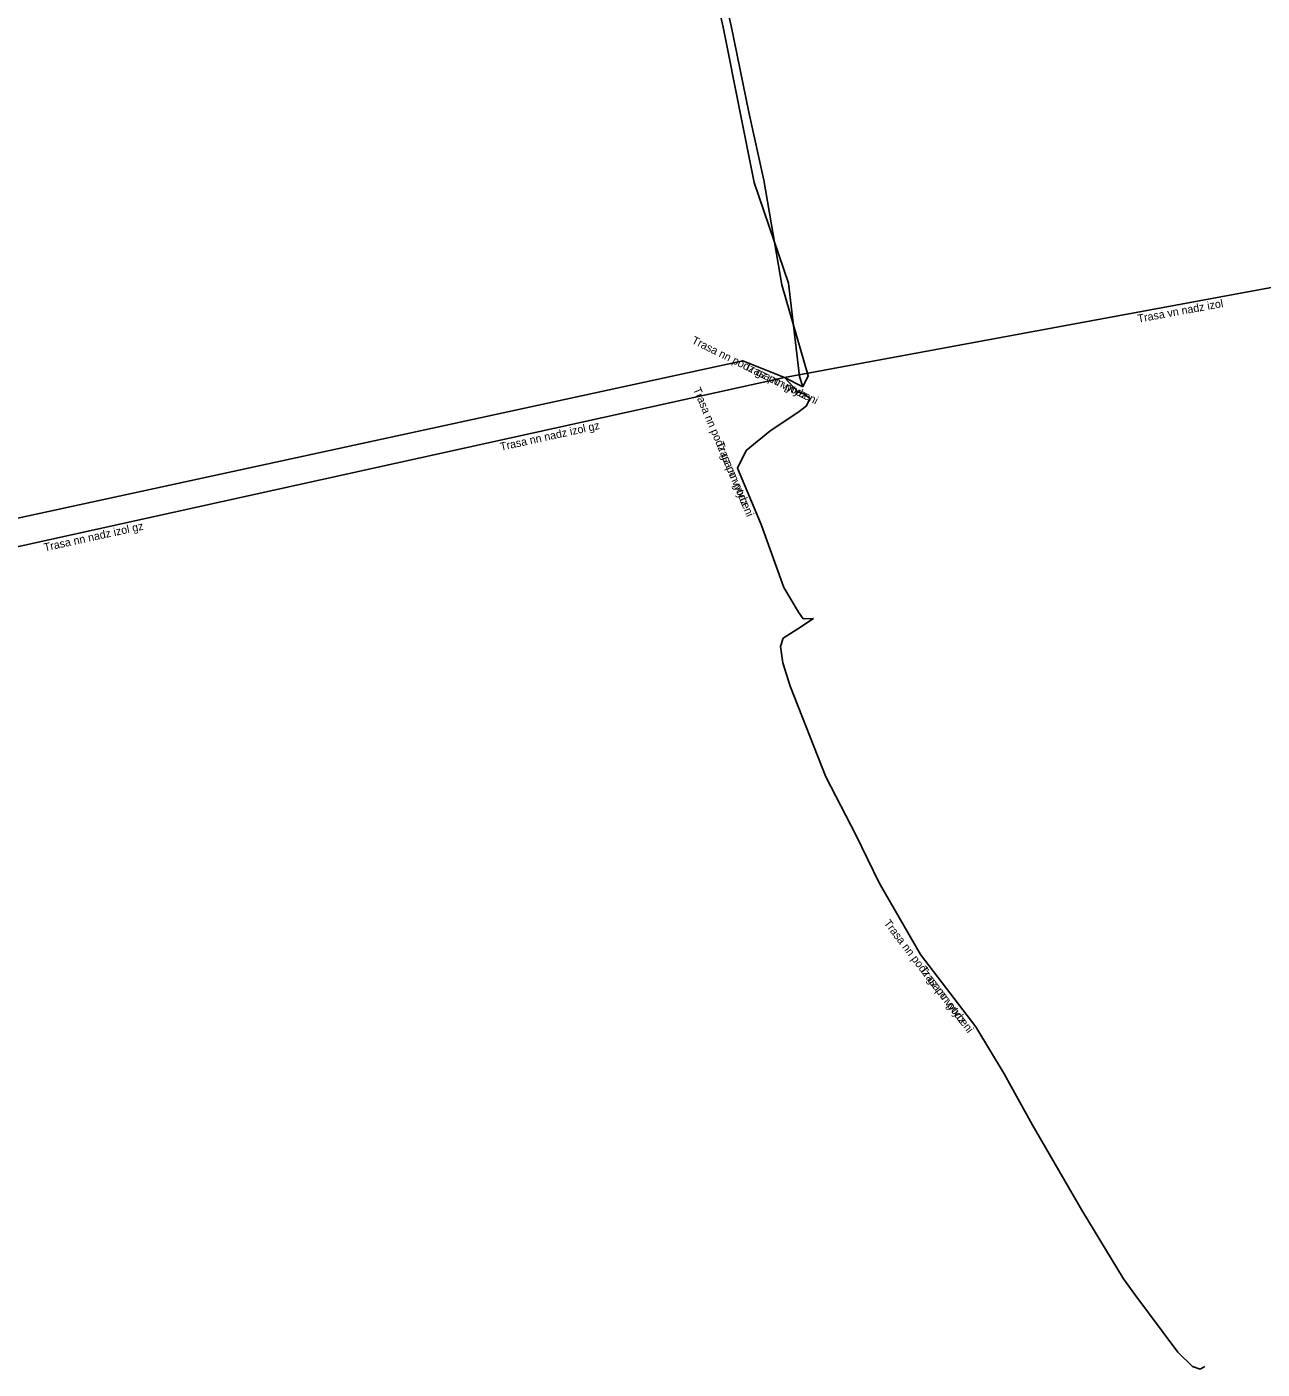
# Model space of a CAD drawing. Extents: x -876384 to -875659, y -1020218 to -1019588.
# Drawn here: x -876045.3 to -875968.1, y -1020120.4 to -1020036.5 of the extents above; entities that cross this region are included whole.
import ezdxf

# ---------------------------------------------------------------- set-up
doc = ezdxf.new("R2010")
doc.units = 0
for name, color, linetype in [('Popiskový text - Ostatní atributy Trasy', 7, 'Continuous'), ('Spojnice NN', 7, 'Continuous'), ('Spojnice VN', 7, 'Continuous')]:
    doc.layers.add(name, color=color, linetype=linetype)

msp = doc.modelspace()

# ---------------------------------------------------------------- linework, layer by layer
at = {"layer": 'Spojnice NN'}
for points in [[(-876006.23, -1020010.08), (-876006.58, -1020010.47), (-876007.09, -1020011.09), (-876007.16, -1020012.14), (-876006.39, -1020017.14), (-876004.42, -1020023.09), (-876003.38, -1020029.52), (-876001.78, -1020036.52), (-876000.71, -1020041.94), (-875999.84, -1020046.22), (-875997.71, -1020052.52), (-875997.02, -1020058.35), (-875996.81, -1020058.98)], [(-876006.23, -1020010.08), (-876006.58, -1020010.47), (-876007.09, -1020011.09), (-876007.16, -1020012.14), (-876006.39, -1020017.14), (-876004.42, -1020023.09), (-876003.38, -1020029.52), (-876001.78, -1020036.52), (-876000.71, -1020041.94), (-875999.84, -1020046.22), (-875997.71, -1020052.52), (-875997.02, -1020058.35), (-875996.81, -1020058.98)], [(-876007.97, -1020010.49), (-876007.54, -1020010.71), (-876007.4, -1020011.1), (-876006.73, -1020012.04), (-876005.81, -1020016.98), (-876004.99, -1020023.28), (-876002.91, -1020029.39), (-876001.28, -1020036.42), (-876000.18, -1020041.82), (-875999.24, -1020046.07), (-875998.13, -1020052.62), (-875996.48, -1020058.31), (-875996.81, -1020058.98)], [(-876007.97, -1020010.49), (-876007.54, -1020010.71), (-876007.4, -1020011.1), (-876006.73, -1020012.04), (-876005.81, -1020016.98), (-876004.99, -1020023.28), (-876002.91, -1020029.39), (-876001.28, -1020036.42), (-876000.18, -1020041.82), (-875999.24, -1020046.07), (-875998.13, -1020052.62), (-875996.48, -1020058.31), (-875996.81, -1020058.98)], [(-875997.96, -1020058.41), (-876000.56, -1020057.361), (-876056.756, -1020069.559), (-876061.786, -1020045.119), (-876078.132, -1020047.398)], [(-875997.96, -1020058.41), (-876023.64, -1020064.08)], [(-875997.96, -1020058.41), (-875997.12, -1020059.31), (-875996.71, -1020059.45), (-875996.38, -1020059.71), (-875996.57, -1020060.18), (-875997.03, -1020060.54), (-875998.87, -1020061.76), (-876000.35, -1020062.96), (-876000.89, -1020064.08), (-875999.41, -1020067.59), (-875998, -1020071.53), (-875997.07, -1020073.08), (-875996.78, -1020073.49), (-875996.15, -1020073.47)], [(-875997.96, -1020058.41), (-875997.12, -1020059.31), (-875996.71, -1020059.45), (-875996.38, -1020059.71), (-875996.57, -1020060.18), (-875997.03, -1020060.54), (-875998.87, -1020061.76), (-876000.35, -1020062.96), (-876000.89, -1020064.08), (-875999.41, -1020067.59), (-875998, -1020071.53), (-875997.07, -1020073.08), (-875996.78, -1020073.49), (-875996.15, -1020073.47)], [(-875996.81, -1020058.98), (-875997.96, -1020058.41)], [(-875996.81, -1020058.98), (-875997.96, -1020058.41)], [(-876023.64, -1020064.08), (-876054.99, -1020070.99)], [(-875971.68, -1020120.21), (-875971.98, -1020120.38), (-875972.46, -1020120.22), (-875973.36, -1020119.31), (-875976.05, -1020115.72), (-875976.76, -1020114.74), (-875979.36, -1020110.44), (-875982.47, -1020105.08), (-875984.23, -1020101.93), (-875985.99, -1020098.99), (-875989.46, -1020094.46), (-875992.03, -1020089.98), (-875993.49, -1020086.98), (-875995.36, -1020083.36), (-875997.6, -1020077.69), (-875998.05, -1020076.23), (-875998.21, -1020075.22), (-875998.04, -1020074.69), (-875997.13, -1020074.12), (-875996.15, -1020073.47)], [(-875971.68, -1020120.21), (-875971.98, -1020120.38), (-875972.46, -1020120.22), (-875973.36, -1020119.31), (-875976.05, -1020115.72), (-875976.76, -1020114.74), (-875979.36, -1020110.44), (-875982.47, -1020105.08), (-875984.23, -1020101.93), (-875985.99, -1020098.99), (-875989.46, -1020094.46), (-875992.03, -1020089.98), (-875993.49, -1020086.98), (-875995.36, -1020083.36), (-875997.6, -1020077.69), (-875998.05, -1020076.23), (-875998.21, -1020075.22), (-875998.04, -1020074.69), (-875997.13, -1020074.12), (-875996.15, -1020073.47)]]:
    msp.add_lwpolyline(points, dxfattribs=at)
at = {"layer": 'Spojnice VN'}
msp.add_lwpolyline([(-875945.314, -1020048.682), (-875997.96, -1020058.41)], dxfattribs=at)

# ---------------------------------------------------------------- texts
at = {"layer": 'Popiskový text - Ostatní atributy Trasy'}
for s, rotation, p in [('Trasa vn nadz izol', 10.469, (-875975.835, -1020054.982)), ('Trasa nn podz gz po vytyceni', 333.63458, (-876003.796, -1020056.243)), ('Trasa nn podz', 333.63458, (-876000.494, -1020057.879)), ('Trasa nn podz gz po vytyceni', 292.86284, (-876003.677, -1020059.143)), ('Trasa nn nadz izol gz', 12.45083, (-876015.675, -1020062.987)), ('Trasa nn podz', 292.86284, (-876002.245, -1020062.539)), ('Trasa nn nadz izol gz', 12.43008, (-876044.191, -1020069.276)), ('Trasa nn podz gz po vytyceni', 307.45227, (-875991.771, -1020092.512)), ('Trasa nn podz', 307.45227, (-875989.531, -1020095.437))]:
    msp.add_text(s, height=0.5, rotation=rotation, dxfattribs=at).set_placement(p)

doc.saveas('drawing.dxf')
